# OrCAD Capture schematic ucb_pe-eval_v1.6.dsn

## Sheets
1 Interface-Power: size C; title: NCREPT PE-Eval PCB; rev: 1.5; company: University of Arkansas (NCREPT); note: 700 W. Research Center Blvd; note: Fayetteville, AR 72701
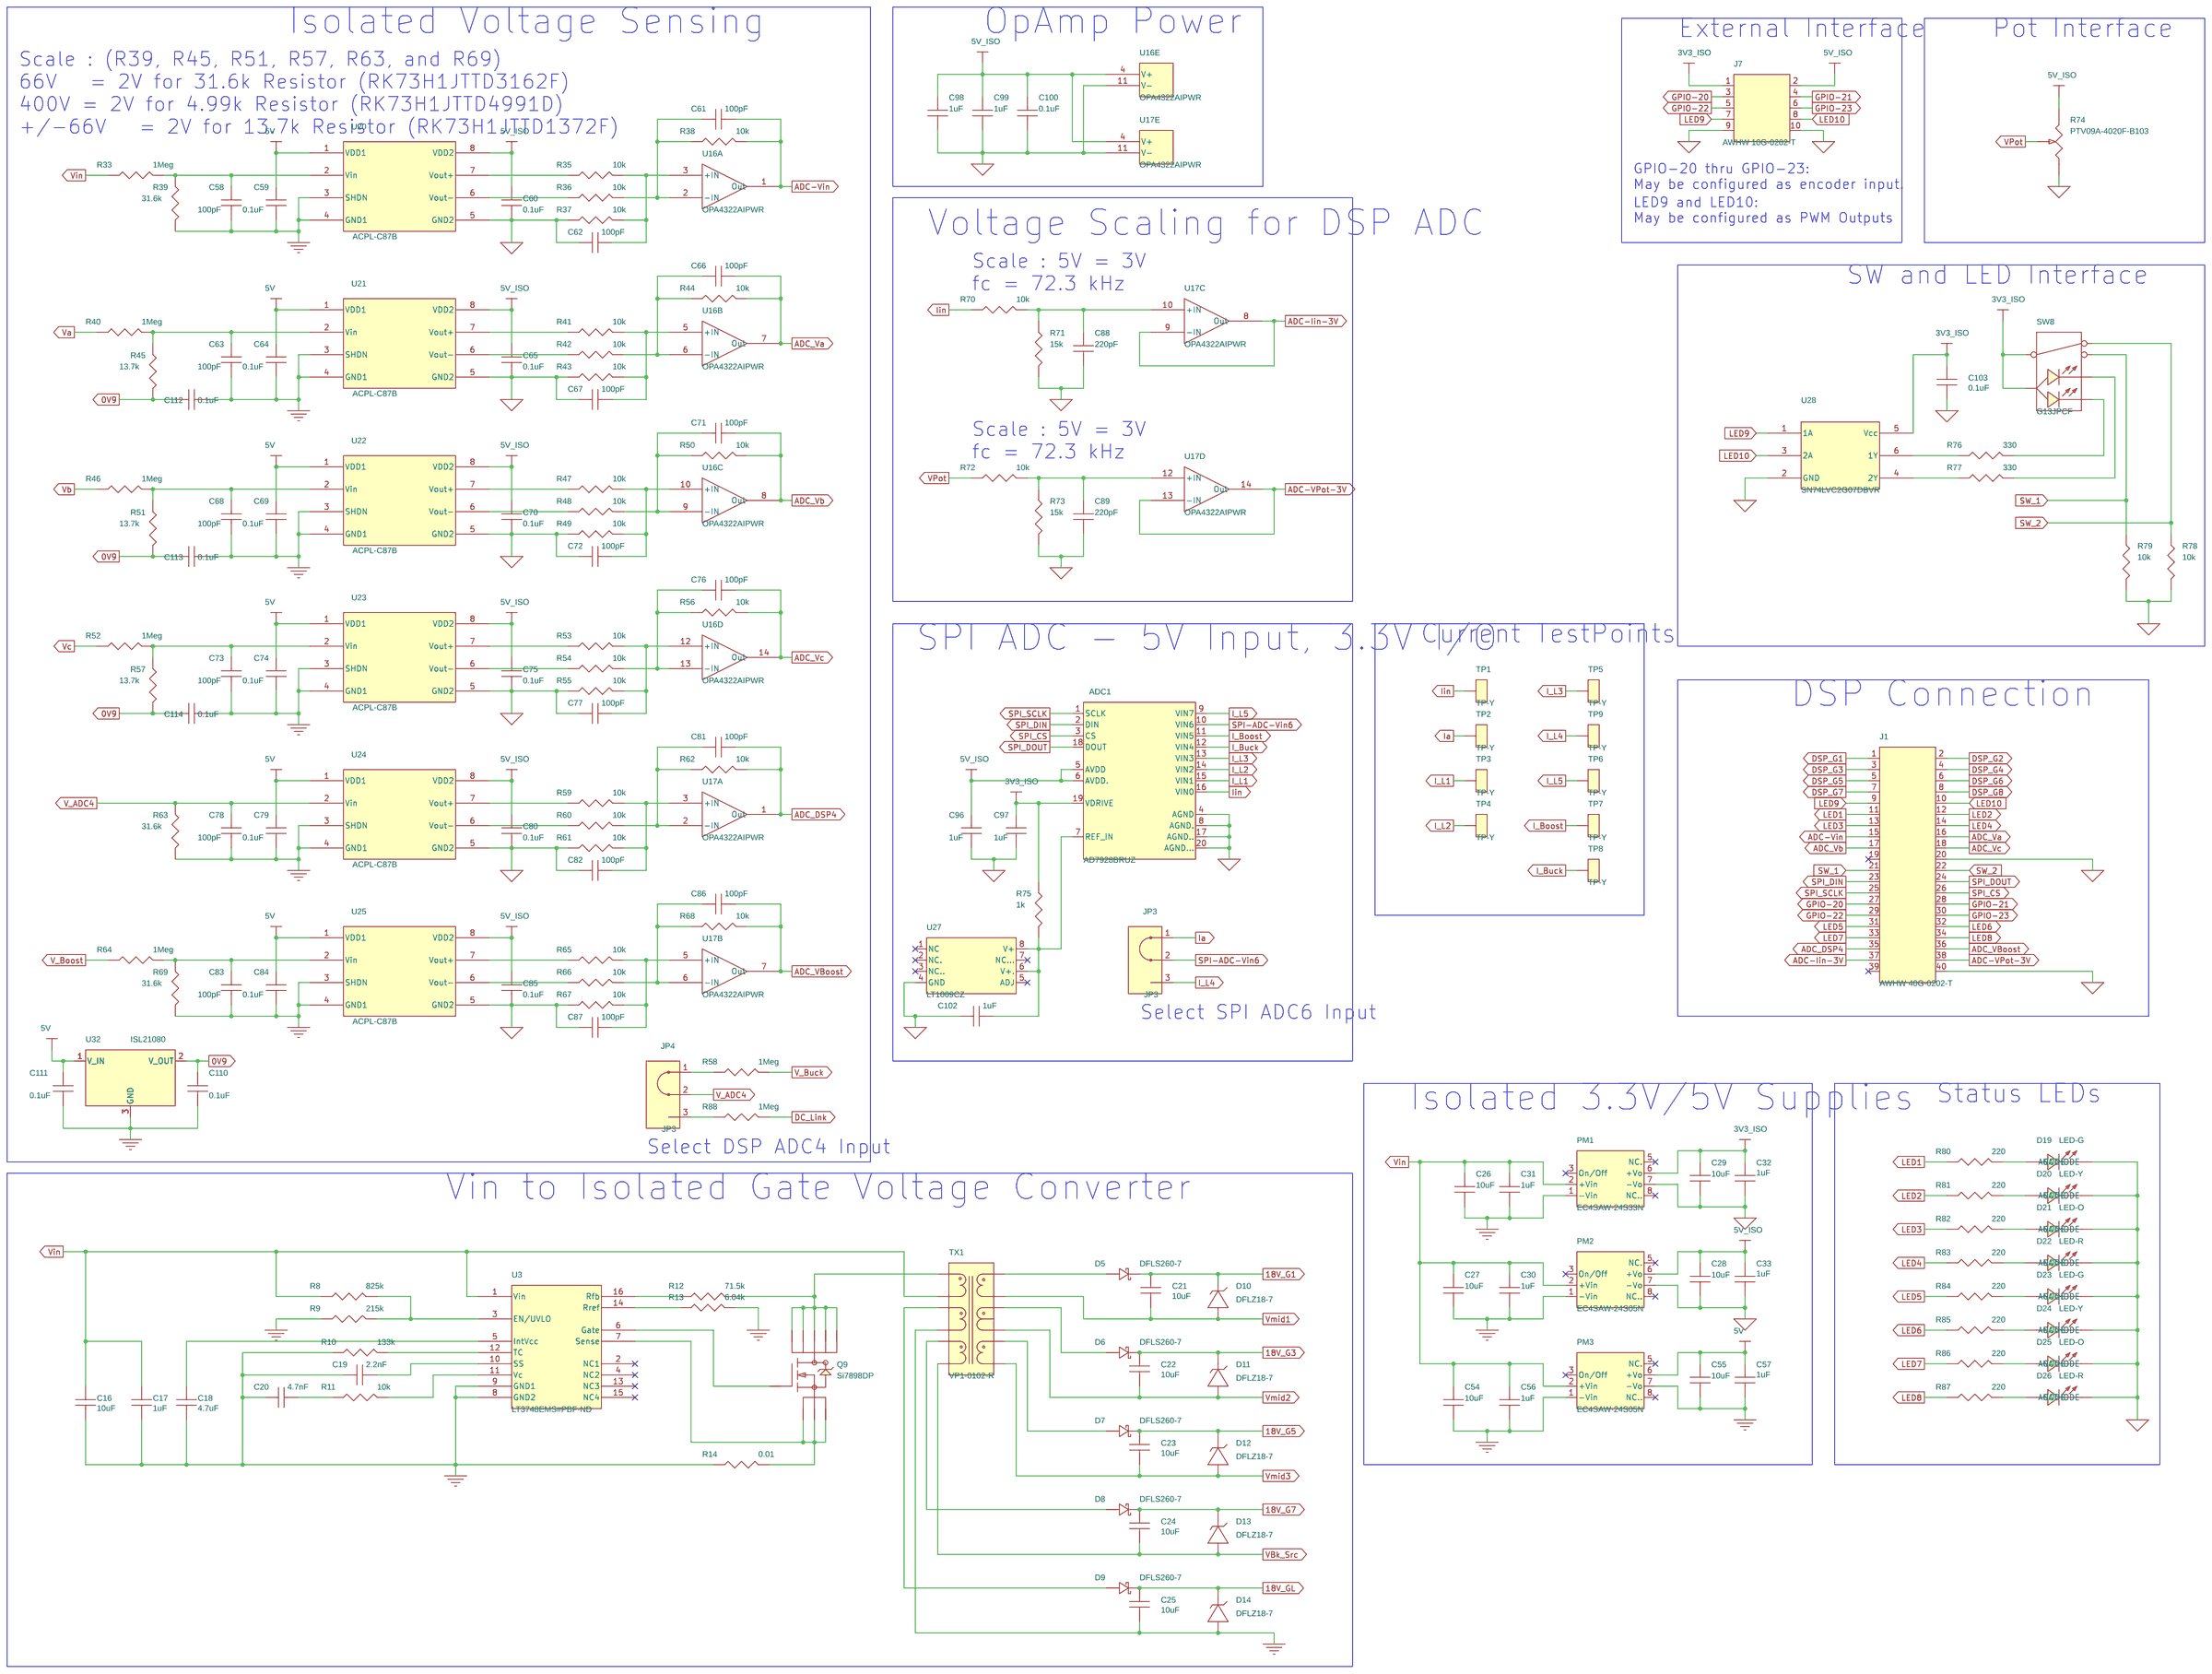
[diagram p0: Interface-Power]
2 Converters: size C
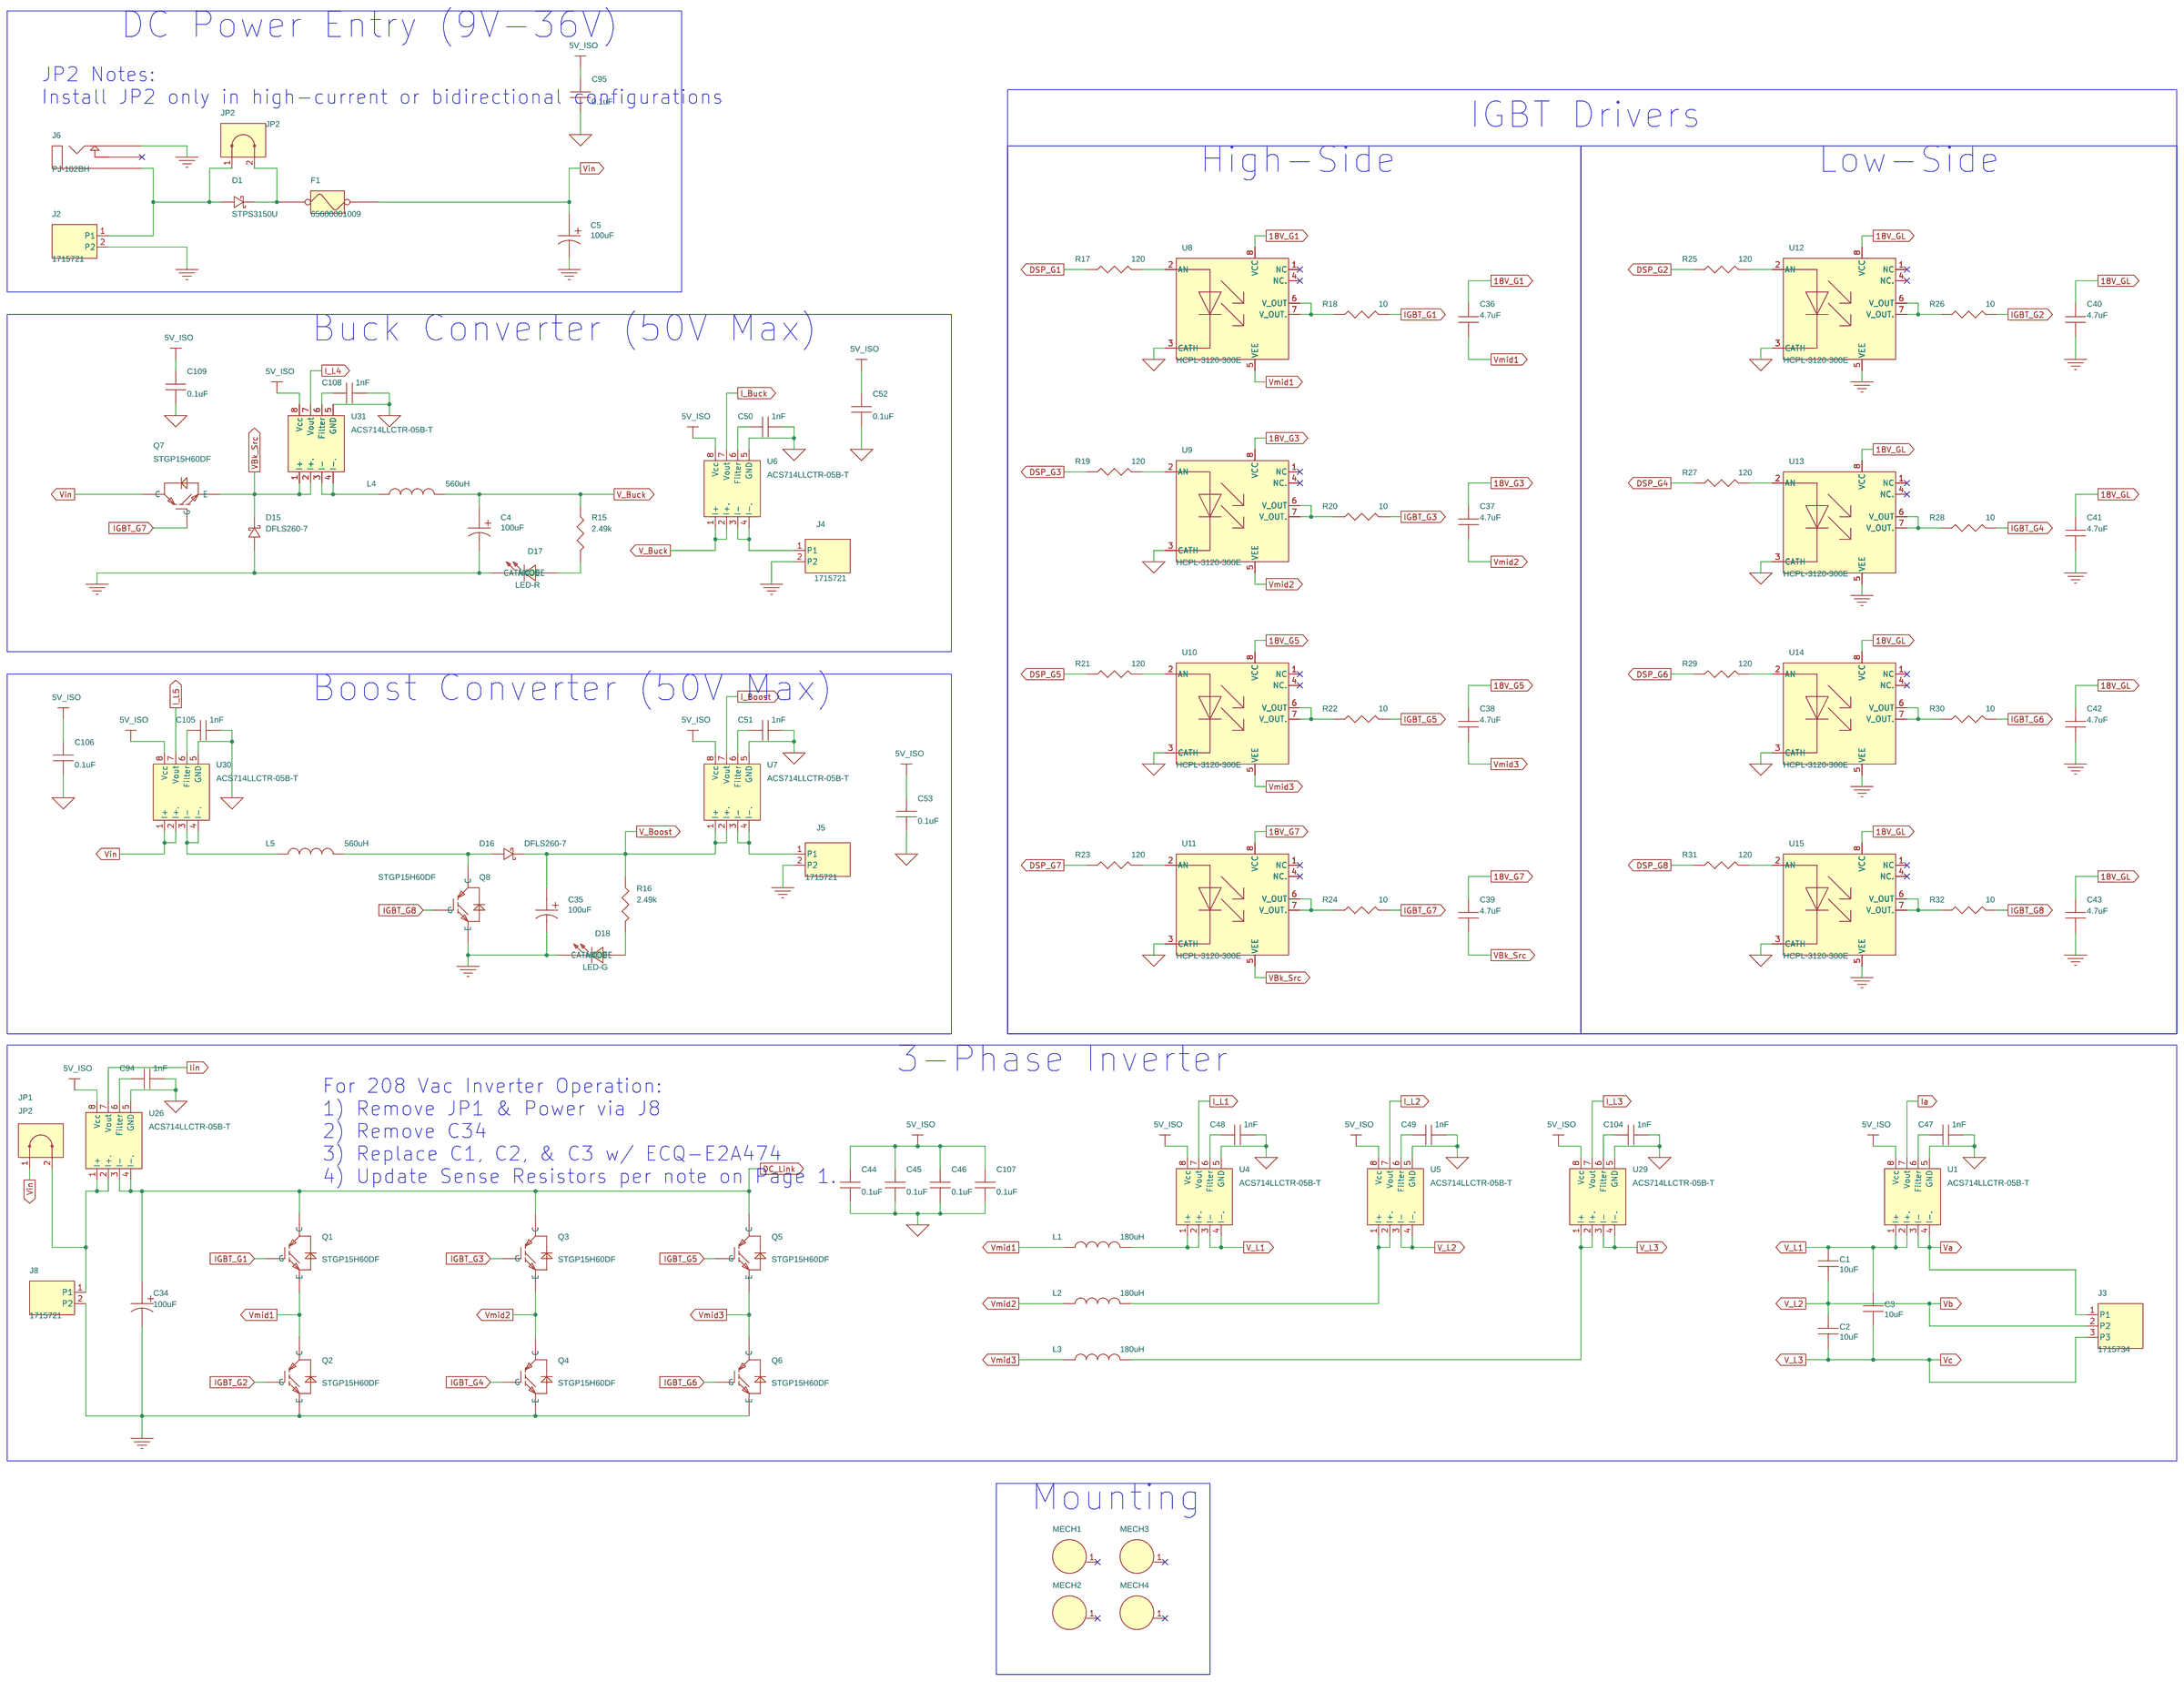
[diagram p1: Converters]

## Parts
sheet Converters
C1  10uF  [ECQ-E2106KFB]
C2  10uF  [ECQ-E2106KFB]
C3  10uF  [ECQ-E2106KFB]
C4  100uF  [UVZ1H101MPD]
C5  100uF  [UVZ1H101MPD]
C34  100uF  [UVZ1H101MPD]
C35  100uF  [UVZ1H101MPD]
C36  4.7uF  [C_1206]
C37  4.7uF  [C_1206]
C38  4.7uF  [C_1206]
C39  4.7uF  [C_1206]
C40  4.7uF  [C_1206]
C41  4.7uF  [C_1206]
C42  4.7uF  [C_1206]
C43  4.7uF  [C_1206]
C44  0.1uF  [C_0603]
C45  0.1uF  [C_0603]
C46  0.1uF  [C_0603]
C47  1nF  [C_0603]
C48  1nF  [C_0603]
C49  1nF  [C_0603]
C50  1nF  [C_0603]
C51  1nF  [C_0603]
C52  0.1uF  [C_0603]
C53  0.1uF  [C_0603]
C94  1nF  [C_0603]
C95  0.1uF  [C_0603]
C104  1nF  [C_0603]
C105  1nF  [C_0603]
C106  0.1uF  [C_0603]
C107  0.1uF  [C_0603]
C108  1nF  [C_0603]
C109  0.1uF  [C_0603]
D1  STPS3150U  [DO-214AA_SMB]
D15  DFLS260-7  [PowerDI-123]
D16  DFLS260-7  [PowerDI-123]
D17  LED-R  [LED_0805-RED]
D18  LED-G  [LED_0805-GREEN]
F1  65600001009  [FUSE_5X20MM]
J2  1715721  [1715721]
J3  1715734  [1715734]
J4  1715721  [1715721]
J5  1715721  [1715721]
J6  PJ-102BH  [DC-PWR_JACK]
J8  1715721  [1715721]
JP1  JP2  [J_1X2]
JP2  JP2  [J_1X2]
L1  180uH  [PCV-2-184-05L]
L2  180uH  [PCV-2-184-05L]
L3  180uH  [PCV-2-184-05L]
L4  560uH  [PCV-2-564-02L]
L5  560uH  [PCV-2-564-02L]
MECH1  Mech_Hole  [4-40_SCREW]
MECH2  Mech_Hole  [4-40_SCREW]
MECH3  Mech_Hole  [4-40_SCREW]
MECH4  Mech_Hole  [4-40_SCREW]
Q1  STGP15H60DF  [TO-220]
Q2  STGP15H60DF  [TO-220]
Q3  STGP15H60DF  [TO-220]
Q4  STGP15H60DF  [TO-220]
Q5  STGP15H60DF  [TO-220]
Q6  STGP15H60DF  [TO-220]
Q7  STGP15H60DF  [TO-220]
Q8  STGP15H60DF  [TO-220]
R15  2.49k  [R_2512]
R16  2.49k  [R_2512]
R17  120  [R_1206]
R18  10  [R_1206]
R19  120  [R_1206]
R20  10  [R_1206]
R21  120  [R_1206]
R22  10  [R_1206]
R23  120  [R_1206]
R24  10  [R_1206]
R25  120  [R_1206]
R26  10  [R_1206]
R27  120  [R_1206]
R28  10  [R_1206]
R29  120  [R_1206]
R30  10  [R_1206]
R31  120  [R_1206]
R32  10  [R_1206]
U1  ACS714LLCTR-05B-T  [8-SOIC]
U4  ACS714LLCTR-05B-T  [8-SOIC]
U5  ACS714LLCTR-05B-T  [8-SOIC]
U6  ACS714LLCTR-05B-T  [8-SOIC]
U7  ACS714LLCTR-05B-T  [8-SOIC]
U8  HCPL-3120-300E  [8-DIP_GW]
U9  HCPL-3120-300E  [8-DIP_GW]
U10  HCPL-3120-300E  [8-DIP_GW]
U11  HCPL-3120-300E  [8-DIP_GW]
U12  HCPL-3120-300E  [8-DIP_GW]
U13  HCPL-3120-300E  [8-DIP_GW]
U14  HCPL-3120-300E  [8-DIP_GW]
U15  HCPL-3120-300E  [8-DIP_GW]
U26  ACS714LLCTR-05B-T  [8-SOIC]
U29  ACS714LLCTR-05B-T  [8-SOIC]
U30  ACS714LLCTR-05B-T  [8-SOIC]
U31  ACS714LLCTR-05B-T  [8-SOIC]
sheet Interface-Power
ADC1  AD7928BRUZ  [20-TSSOP]
C16  10uF  [C_1206]
C17  1uF  [C_0603]
C18  4.7uF  [C_1206]
C19  2.2nF  [C_0603]
C20  4.7nF  [C_0603]
C21  10uF  [C_1206]
C22  10uF  [C_1206]
C23  10uF  [C_1206]
C24  10uF  [C_1206]
C25  10uF  [C_1206]
C26  10uF  [C_1206]
C27  10uF  [C_1206]
C28  10uF  [C_1206]
C29  10uF  [C_1206]
C30  1uF  [C_0603]
C31  1uF  [C_0603]
C32  1uF  [C_0603]
C33  1uF  [C_0603]
C54  10uF  [C_1206]
C55  10uF  [C_1206]
C56  1uF  [C_0603]
C57  1uF  [C_0603]
C58  100pF  [C_0603]
C59  0.1uF  [C_0603]
C60  0.1uF  [C_0603]
C61  100pF  [C_0603]
C62  100pF  [C_0603]
C63  100pF  [C_0603]
C64  0.1uF  [C_0603]
C65  0.1uF  [C_0603]
C66  100pF  [C_0603]
C67  100pF  [C_0603]
C68  100pF  [C_0603]
C69  0.1uF  [C_0603]
C70  0.1uF  [C_0603]
C71  100pF  [C_0603]
C72  100pF  [C_0603]
C73  100pF  [C_0603]
C74  0.1uF  [C_0603]
C75  0.1uF  [C_0603]
C76  100pF  [C_0603]
C77  100pF  [C_0603]
C78  100pF  [C_0603]
C79  0.1uF  [C_0603]
C80  0.1uF  [C_0603]
C81  100pF  [C_0603]
C82  100pF  [C_0603]
C83  100pF  [C_0603]
C84  0.1uF  [C_0603]
C85  0.1uF  [C_0603]
C86  100pF  [C_0603]
C87  100pF  [C_0603]
C88  220pF  [C_0603]
C89  220pF  [C_0603]
C96  1uF  [C_0603]
C97  1uF  [C_0603]
C98  1uF  [C_0603]
C99  1uF  [C_0603]
C100  0.1uF  [C_0603]
C102  1uF  [C_0603]
C103  0.1uF  [C_0603]
C110  0.1uF  [C_0603]
C111  0.1uF  [C_0603]
C112  0.1uF  [C_0603]
C113  0.1uF  [C_0603]
C114  0.1uF  [C_0603]
D5  DFLS260-7  [PowerDI-123]
D6  DFLS260-7  [PowerDI-123]
D7  DFLS260-7  [PowerDI-123]
D8  DFLS260-7  [PowerDI-123]
D9  DFLS260-7  [PowerDI-123]
D10  DFLZ18-7  [PowerDI-123]
D11  DFLZ18-7  [PowerDI-123]
D12  DFLZ18-7  [PowerDI-123]
D13  DFLZ18-7  [PowerDI-123]
D14  DFLZ18-7  [PowerDI-123]
D19  LED-G  [LED_0805-GREEN]
D20  LED-Y  [LED_0805-YELLOW]
D21  LED-O  [LED_0805-ORANGE]
D22  LED-R  [LED_0805-RED]
D23  LED-G  [LED_0805-GREEN]
D24  LED-Y  [LED_0805-YELLOW]
D25  LED-O  [LED_0805-ORANGE]
D26  LED-R  [LED_0805-RED]
J1  AWHW 40G-0202-T  [40-IDC-M]
J7  AWHW 10G-0202-T  [10-IDC-M]
JP3  JP3  [J_1X3]
JP4  JP3  [J_1X3]
PM1  EC4SAW-24S33N  [SIP-8]
PM2  EC4SAW-24S05N  [SIP-8]
PM3  EC4SAW-24S05N  [SIP-8]
Q9  Si7898DP  [SO-8_PP]
R8  825k  [R_0603]
R9  215k  [R_0603]
R10  133k  [R_0603]
R11  10k  [R_0603]
R12  71.5k  [R_0603]
R13  6.04k  [R_0603]
R14  0.01  [R_1206]
R33  1Meg  [R_1206]
R35  10k  [R_0603]
R36  10k  [R_0603]
R37  10k  [R_0603]
R38  10k  [R_0603]
R39  31.6k  [R_0805]
R40  1Meg  [R_1206]
R41  10k  [R_0603]
R42  10k  [R_0603]
R43  10k  [R_0603]
R44  10k  [R_0603]
R45  13.7k  [R_0603]
R46  1Meg  [R_1206]
R47  10k  [R_0603]
R48  10k  [R_0603]
R49  10k  [R_0603]
R50  10k  [R_0603]
R51  13.7k  [R_0603]
R52  1Meg  [R_1206]
R53  10k  [R_0603]
R54  10k  [R_0603]
R55  10k  [R_0603]
R56  10k  [R_0603]
R57  13.7k  [R_0603]
R58  1Meg  [R_1206]
R59  10k  [R_0603]
R60  10k  [R_0603]
R61  10k  [R_0603]
R62  10k  [R_0603]
R63  31.6k  [R_0805]
R64  1Meg  [R_1206]
R65  10k  [R_0603]
R66  10k  [R_0603]
R67  10k  [R_0603]
R68  10k  [R_0603]
R69  31.6k  [R_0805]
R70  10k  [R_0603]
R71  15k  [R_0603]
R72  10k  [R_0603]
R73  15k  [R_0603]
R74  PTV09A-4020F-B103  [9MM_POT]
R75  1k  [R_0805]
R76  330  [R_0805]
R77  330  [R_0805]
R78  10k  [R_0603]
R79  10k  [R_0603]
R80  220  [R_0805]
R81  220  [R_0805]
R82  220  [R_0805]
R83  220  [R_0805]
R84  220  [R_0805]
R85  220  [R_0805]
R86  220  [R_0805]
R87  220  [R_0805]
R88  1Meg  [R_1206]
SW8  G13JPCF  [G13JPCF_TH]
TP1  TP-Y  [TP-YELLOW]
TP2  TP-Y  [TP-YELLOW]
TP3  TP-Y  [TP-YELLOW]
TP4  TP-Y  [TP-YELLOW]
TP5  TP-Y  [TP-YELLOW]
TP6  TP-Y  [TP-YELLOW]
TP7  TP-Y  [TP-YELLOW]
TP8  TP-Y  [TP-YELLOW]
TP9  TP-Y  [TP-YELLOW]
TX1  VP1-0102-R  [TX-VP1]
U3  LT3748EMS#PBF-ND  [16-MSOP]
U16  OPA4322AIPWR  [OPA4332_14-TSSOP]  (sections A,B,C,D,E)
U17  OPA4322AIPWR  [OPA4332_14-TSSOP]  (sections A,B,C,D,E)
U20  ACPL-C87B  [ACPL-C87X]
U21  ACPL-C87B  [ACPL-C87X]
U22  ACPL-C87B  [ACPL-C87X]
U23  ACPL-C87B  [ACPL-C87X]
U24  ACPL-C87B  [ACPL-C87X]
U25  ACPL-C87B  [ACPL-C87X]
U27  LT1009CZ  [8-MSOP]
U28  SN74LVC2G07DBVR  [SOT-23-6]
U32  ISL21080  [SOT_23-3]

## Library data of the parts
C1-C3 = CAP_NP: Film Capacitor, 10uF, 250Vdc; Manufacturer: Panasonic; Part_Number: Cap-00019; Tolerance: 10%; Voltage: 250V; Datasheet: Panasonic-ABD0000C179-947645.pdf
C4 C5 C34 C35 = CAP_P: Electrolytic Capacitor (50V/100uF); Manufacturer: Nichicon; Part_Number: Cap-00020; Voltage: 50V; Datasheet: Nicicon-e-uvz-880014.pdf
C18 C36-C43 = CAP_NP: 4.7µF ±10% 50V X7R MLCC; Manufacturer: TDK; Manufacturer_Part_Number: C3216X7R1H475K160AC; Part_Number: Cap-00015; Tolerance: 10%; Voltage: 50V; Datasheet: TDK-mlcc_commercial_general_en.pdf
C44-C46 C52 C53 C59 C60 C64 C65 C69 C70 C74 C75 C79 C80 C84 C85 C95 C100 C103 C106 C107 C109-C114 = CAP_NP: 0.1µF ±10% 50V X7R MLCC; Manufacturer: TDK; Manufacturer_Part_Number: C1608X7R1H104K080AA; Part_Number: Cap-00001; Tolerance: 10%; Voltage: 50V; Datasheet: TDK-mlcc_commercial_general_en.pdf
C47-C51 C94 C104 C105 C108 = CAP_NP: 1nF ±10% 100V X7R MLCC; Manufacturer: TDK; Manufacturer_Part_Number: C1608X7R2A102K080AA; Part_Number: Cap-00005; Tolerance: 10%; Voltage: 100V; Datasheet: TDK-mlcc_commercial_general_en.pdf
D1 = D-Schottky: Schottky Diode 3A/150V; Manufacturer: ST; Part_Number: D-00001; STEP_Model: Diode SMA.stp; Datasheet: ST-en.CD00003323.pdf
D5-D9 D15 D16 = D-Schottky: Schottky Diode 2A/60V; Manufacturer: Diodes Incorporated; Part_Number: D-00005; STEP_Model: POWERDI-123.stp; Datasheet: DiodesInc-ds31476-56424.pdf
D17 D22 D26 = LED: LED, 0805, Red, VF= 1.8V; Manufacturer: OSRAM; Manufacturer_Part_Number: LH R974-LP-1; Part_Number: D-00007; STEP_Model: LED_0805-Red.stp; Datasheet: OSRAM-LHR974-CHIPLED0805-318659.pdf
D18 D19 D23 = LED: LED, 0805, Green, VF= 2.2V; Manufacturer: OSRAM; Manufacturer_Part_Number: LG R971-KN-1; Part_Number: D-00008; STEP_Model: LED_0805-Green.stp; Datasheet: OSRAM-LGR971-CHIPLED-0805-318376.pdf
F1 = FUSEHOLDER: Fuse Holder, 5x20mm, TH; Manufacturer: Littelfuse; Part_Number: F-00001; Datasheet: Littelfuse-656_659_660_LF_060102-16982.pdf
J2 J4 J5 J8 = Connector-2: PCB Terminal Block, 2-position, 90 degrees, 5.08mm; Manufacturer: Phoenix Contact; Part_Number: Con-00006; Rating: 17.5A; STEP_Model: 1715721.stp; Voltage: 400V; Datasheet: PhoenixContact-1715734.pdf
J3 = Connector-3: PCB Terminal Block, 3-position, 90 degrees, 5.08mm; Manufacturer: Phoenix Contact; Part_Number: Con-00007; Rating: 17.5A; STEP_Model: 1715734.stp; Voltage: 400V; Datasheet: PhoenixContact-1715734.pdf
J6 = DC-Jack_3: DC Power Jack, 2.5mm Center Pin, TH; Manufacturer: CUI; Part_Number: Con-00017; STEP_Model: pj-102bh.stp; Datasheet: CUI-PJ-102BH-524153.pdf
JP1 JP2 = JP2: Male, TH, Straight, 2-Pos, 0.1" Pitch; Manufacturer: Various; Manufacturer_Part_Number: PRT-00116; Part_Number: JP-00001
L1-L3 = Ind: 180uH, 4.0A, PCV-2; Manufacturer: CoilCraft; Part_Number: Ind-00009; Rating: 4A; Tolerance: 10%; Datasheet: CoilCraft-pcv.pdf
L4 L5 = Ind: 560uH, 2.6A, PCV-2; Manufacturer: CoilCraft; Part_Number: Ind-00010; Rating: 2.6A; Tolerance: 10%; Datasheet: CoilCraft-pcv.pdf
MECH1-MECH4 = Mech_Hole: Mounting Hole for 4-40 Screw, 0.125"; Part_Number: Con-00005
Q1-Q8 = IGBT_TO220: IGBT Trench gate 600V 15A; Manufacturer: STMicroelectrionics; Part_Number: Q-00004; STEP_Model: TO-220 3pins short V1.stp; Datasheet: ST-stgb15h60df-955853.pdf
R15 R16 = R-Standard: 2.49k Ohm, 1%, 2512; Manufacturer: KOA Speer; Manufacturer_Part_Number: RK73H3ATTE2491F; Part_Number: Res-00044; Rating: 1W; Tolerance: 1%; Datasheet: KOA-RK73H-5715.pdf
R17 R19 R21 R23 R25 R27 R29 R31 = R-Standard: 120 Ohm, 1%, 1206; Manufacturer: KOA Speer; Manufacturer_Part_Number: RK73H2BTTD1200F; Part_Number: Res-00041; Rating: 0.25W; Tolerance: 1%; Datasheet: KOA-RK73H-5715.pdf
R18 R20 R22 R24 R26 R28 R30 R32 = R-Standard: 10 Ohm, 1%, 1206; Manufacturer: KOA Speer; Manufacturer_Part_Number: RK73H2BTTD10R0F; Part_Number: Res-00008; Rating: 0.25W; Tolerance: 1%; Datasheet: KOA-RK73H-5715.pdf
U1 U4-U7 U26 U29-U31 = ACS714: Hall Effect Sensor, 5A AC/DC,185mV/A; Manufacturer: Allegro; Part_Number: IC-00016; Tolerance: 1.50%; Datasheet: Allegro-ACS714-Datasheet.pdf
U8-U15 = HCPL-3120: 2.5 Amp  IGBT Gate Drive, Optocoupler, Gullwing; Manufacturer: Avago; Part_Number: IC-00022; STEP_Model: 8-pin-DIP_GW_HCPL-300E.stp; Datasheet: Avago-AV02-0161EN_DS_HCPL-3120_2016-03-21.pdf
ADC1 = AD7928BRUZ: ADC 8-Ch, 12-Bit, 1MSPS; Manufacturer: Analog Devices; Part_Number: IC-00023; STEP_Model: TSSOP65P640X120-20N.stp; Datasheet: AnalogDevices-AD7908_7918_7928-877555.pdf
C16 C21-C29 C54 C55 = CAP_NP: 10µF ±20% 35V X7R MLCC; Manufacturer: TDK; Manufacturer_Part_Number: C3216X7R1V106M160AC; Part_Number: Cap-00002; Tolerance: 20%; Voltage: 35V; Datasheet: TDK-mlcc_commercial_general_en.pdf
C17 C30-C33 C56 C57 C96-C99 C102 = CAP_NP: 1µF ±10% 35V X7R MLCC; Manufacturer: TDK; Manufacturer_Part_Number: C1608X7R1V105K080AC; Part_Number: Cap-00008; Tolerance: 10%; Voltage: 35V; Datasheet: TDK-mlcc_commercial_general_en.pdf
C19 = CAP_NP: 2.2nF ±10% 100V X7R MLCC; Manufacturer: TDK; Manufacturer_Part_Number: C1608X7R2A222K080AA; Part_Number: Cap-00016; Tolerance: 10%; Voltage: 100V; Datasheet: TDK-mlcc_commercial_general_en.pdf
C20 = CAP_NP: 4.7nF ±10% 100V X7R MLCC; Manufacturer: TDK; Manufacturer_Part_Number: C1608X7R2A472K080AA; Part_Number: Cap-00017; Tolerance: 10%; Voltage: 100V; Datasheet: TDK-mlcc_commercial_general_en.pdf
C58 C61-C63 C66-C68 C71-C73 C76-C78 C81-C83 C86 C87 = CAP_NP: 100pF ±10% 100V C0G MLCC; Manufacturer: TDK; Manufacturer_Part_Number: C1608C0G2A101K080AA; Part_Number: Cap-00013; Tolerance: 10%; Voltage: 100V; Datasheet: TDK-mlcc_commercial_general_en.pdf
C88 C89 = CAP_NP: 0.22nF ±5% 100V C0G MLCC; Manufacturer: TDK; Manufacturer_Part_Number: C1608C0G2A221J080AA; Part_Number: Cap-00018; Tolerance: 5%; Voltage: 100V; Datasheet: TDK-mlcc_commercial_general_en.pdf
D10-D14 = D-Zener: Zener Diode 18V 1W; Manufacturer: Diodes Incorporated; Part_Number: D-00003; STEP_Model: POWERDI-123.stp; Tolerance: 6%; Datasheet: DiodesInc-ds30464.pdf
D20 D24 = LED: LED, 0805, Yellow, VF= 2.0V; Manufacturer: OSRAM; Manufacturer_Part_Number: LY R976-PS-36; Part_Number: D-00009; STEP_Model: LED_0805-Yellow.stp; Datasheet: OSRAM-LYR976-CHIPLED0805-318976.pdf
D21 D25 = LED: LED, 0805, Orange, VF= 2.0V; Manufacturer: OSRAM; Manufacturer_Part_Number: LO R976-PS-1; Part_Number: D-00010; STEP_Model: LED_0805-Orange.stp; Datasheet: OSRAM-LOR976-CHIPLED0805-318582.pdf
J1 = Header_2x20: 40-POS Header, Shrouded, 0.100", TH; Manufacturer: Assmann; Part_Number: Con-00015; STEP_Model: HDB-40.stp; User_Field1: SBH11-PBPC-D20-ST-BK; Datasheet: Assmann-AWHW-xxG-0x02-T.pdf
J7 = Header_2x5: 10-POS Header, Shrouded, 0.100", TH; Manufacturer: Assmann; Part_Number: Con-00013; STEP_Model: HDB-10.stp; User_Field1: SBH11-PBPC-D05-ST-BK; Datasheet: Assmann-AWHW-xxG-0x02-T.pdf
JP3 JP4 = JP3: Male, TH, Straight, 3-Pos, 0.1" Pitch; Manufacturer: Various; Manufacturer_Part_Number: PRT-00116; Part_Number: JP-00002
PM1 = EC4SA: Isolated DC/DC Converters 5 Watt, 9-36 Vin, 3.3 Vout; Manufacturer: Cincon; Part_Number: PS-00001; STEP_Model: PwrMod-SIP8.stp; Tolerance: 1.50%; Datasheet: CINCON-EC4SAW V10-557886.pdf
PM2 PM3 = EC4SA: Isolated DC/DC Converters 6 Watt, 9-36 Vin, 5 Vout; Manufacturer: Cincon; Part_Number: PS-00002; STEP_Model: PwrMod-SIP8.stp; Tolerance: 1.50%; Datasheet: CINCON-EC4SAW V10-557886.pdf
Q9 = N-FET_Si7898DP: Si N-Chan MOSFET 150V/3A; Manufacturer: Vishay; Manufacturer_Part_Number: SI7898DP-T1-E3; Part_Number: Q-00003; STEP_Model: SO-8.stp; Datasheet: Vishay-71873.pdf
R8 = R-Standard: 825k Ohm, 1%, 0603; Manufacturer: KOA Speer; Manufacturer_Part_Number: RK73H1JTTD8253F; Part_Number: Res-00025; Rating: 0.1W; Tolerance: 1%; Datasheet: KOA-RK73H-5715.pdf
R9 = R-Standard: 215k Ohm, 1%, 0603; Manufacturer: KOA Speer; Manufacturer_Part_Number: RK73H1JTTD2153F; Part_Number: Res-00057; Rating: 0.1W; Tolerance: 1%; Datasheet: KOA-RK73H-5715.pdf
R10 = R-Standard: 133k Ohm, 1%, 0603; Manufacturer: KOA Speer; Manufacturer_Part_Number: RK73H1JTTD1333F; Part_Number: Res-00030; Rating: 0.1W; Tolerance: 1%; Datasheet: KOA-RK73H-5715.pdf
R11 R35-R38 R41-R44 R47-R50 R53-R56 R59-R62 R65-R68 R70 R72 R78 R79 = R-Standard: 10k Ohm, 1%, 0603; Manufacturer: KOA Speer; Manufacturer_Part_Number: RK73H1JTTD1002F; Part_Number: Res-00031; Rating: 0.1W; Tolerance: 1%; Datasheet: KOA-RK73H-5715.pdf
R12 = R-Standard: 71.5k Ohm, 1%, 0603; Manufacturer: KOA Speer; Manufacturer_Part_Number: RK73H1JTTD7152F; Part_Number: Res-00027; Rating: 0.1W; Tolerance: 1%; Datasheet: KOA-RK73H-5715.pdf
R13 = R-Standard: 6.04k Ohm, 1%, 0603; Manufacturer: KOA Speer; Manufacturer_Part_Number: RK73H1JTTD6041F; Part_Number: Res-00029; Rating: 0.1W; Tolerance: 1%; Datasheet: KOA-RK73H-5715.pdf
R14 = R-Standard: 10m Ohm, 1%, 1206, Current Sense Res; Manufacturer: KOA Speer; Manufacturer_Part_Number: UR73VD2BTTD10L0F; Part_Number: Res-00033; Rating: 0.5W; Tolerance: 1%; Datasheet: KOA-UR73V-770279.pdf
R33 R40 R46 R52 R58 R64 R88 = R-Standard: 1M Ohm, 1%,1206; Manufacturer: KOA Speer; Manufacturer_Part_Number: RK73H2BTTD1004F; Part_Number: Res-00034; Tolerance: 1%; Datasheet: KOA-RK73H-5715.pdf
R39 R63 R69 = R-Standard: 31.6k Ohm, 1%, 0603; Manufacturer: KOA Speer; Manufacturer_Part_Number: RK73H1JTTD3162F; Part_Number: Res-00022; Rating: 0.1W; Tolerance: 1%; Datasheet: KOA-RK73H-5715.pdf
R45 R51 R57 = R-Standard: 13.7k Ohm, 1%, 0603; Manufacturer: KOA Speer; Manufacturer_Part_Number: RK73H1JTTD1372F; Part_Number: TMP-372; Tolerance: 1%; Datasheet: KOA-RK73H-5715.pdf
R71 R73 = R-Standard: 15k Ohm, 1%, 0603; Manufacturer: KOA Speer; Manufacturer_Part_Number: RK73H1JTTD1502F; Part_Number: Res-00037; Rating: 0.1W; Tolerance: 1%; Datasheet: KOA-RK73H-5715.pdf
R74 = R-POT: Potentiometer 10k Linear, 6mm Shaft,TH; Manufacturer: Bourns; Part_Number: Res-00043; Tolerance: 20%; Datasheet: Bourns-tv09-777818.pdf
R75 = R-Standard: 1k Ohm, 1%, 0805; Manufacturer: KOA Speer; Manufacturer_Part_Number: RK73H2ATTD1001F; Part_Number: Res-00012; Rating: 0.125W; Tolerance: 1%; Datasheet: KOA-RK73H-5715.pdf
R76 R77 = R-Standard: 330 Ohm, 1%, 0805; Manufacturer: KOA Speer; Manufacturer_Part_Number: RK73H2ATTD3300F; Part_Number: Res-00040; Rating: 0.125W; Tolerance: 1%; Datasheet: KOA-RK73H-5715.pdf
R80-R87 = R-Standard: 220 Ohm, 1%, 0805; Manufacturer: KOA Speer; Manufacturer_Part_Number: RK73H2ATTD2200F; Part_Number: Res-00017; Rating: 0.125W; Tolerance: 1%; Datasheet: KOA-RK73H-5715.pdf
SW8 = SW_G13JPCF: Switch Toggle, SPDT, R/G LED (TH Pads); Manufacturer: NKK Switches; Part_Number: Sw-00002; Datasheet: NKK-gtogglesilluminated.pdf
TP1-TP9 = TP: PCB Test Point TH Yellow; Manufacturer: Keystone Electronics; Manufacturer_Part_Number: 5004; Part_Number: TP-00005; Datasheet: Keystone-000-5004-741320.pdf
TX1 = TX_VP1-0102-R: 6.5µH, 0.8A, 6-Winding XFMR, VTP1, 20%; Manufacturer: Eaton; Part_Number: XFRM-00002; Tolerance: 20%; Datasheet: Eaton-BUS_Elx_PM_4301_VERSA_PAC.pdf
U3 = LT3748EMS#PBF-ND: Flyback Controller (Used with VP1 Arrays); Manufacturer: Linear Tech; Part_Number: IC-00010; STEP_Model: MSOP-16_MSEP16-12.stp; Datasheet: LT-3748fb.pdf
U16 U17 = OPA4322AIPWR: Quad OpAmp, 20 MHz; Manufacturer: TI; Part_Number: IC-00012; STEP_Model: TSSOP14.stp; User_Field1: https://www.google.com/; Datasheet: TI-opa4322.pdf
U20-U25 = ACPL-C87B: Isolation OpAmp, 100 kHz; Manufacturer: Avago; Manufacturer_Part_Number: ACPL-C87B-000E; Part_Number: IC-00011; STEP_Model: SOIC08 wide.stp; Datasheet: Avago-AV02-3563EN_DS_ACPL-C87x_04Mar2013.pdf
U27 = LT1009CZ: 2.5V Voltage Reference, ±0.2%, SMD; Manufacturer: Linear Tech; Manufacturer_Part_Number: LT1009CMS8#PBF; Part_Number: IC-00024; STEP_Model: MSOP8.stp; Tolerance: 0.20%; Datasheet: LinearTech-1009ff.pdf
U28 = SN74LVC2G07DBV: Dual Open-Drain Buffer; Manufacturer: TI; Part_Number: IC-00013; STEP_Model: SOT23-6.stp; Datasheet: TI-sn74lvc2g07.pdf
U32 = ISL21080: 0.9V Voltage Reference, ±0.7%; Manufacturer: Intersil; Manufacturer_Part_Number: ISL21080DIH309Z-TK; Part_Number: IC-00014; Tolerance: 0.70%; Datasheet: Intersil-isl21080.pdf

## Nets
0V9: C110.1 C112.1 C113.1 C114.1 R45.2 R51.2 R57.2 U32.2(V_OUT)
3V3_Iso: ADC1.19(VDRIVE) C29.1 C32.1 C97.1 C103.1 J7.1 PM1.6(+Vo) R75.1 SW8.2(COMMON) SW8.5(CA) U28.5(Vcc)
5V: C55.1 C57.1 C59.1 C64.1 C69.1 C74.1 C79.1 C84.1 C111.1 PM3.6(+Vo) U20.1(VDD1) U21.1(VDD1) U22.1(VDD1) U23.1(VDD1) U24.1(VDD1) U25.1(VDD1) U32.1(V_IN)
5V_Iso: ADC1.5(AVDD) ADC1.6(AVDD.) C28.1 C33.1 C44.1 C45.1 C46.1 C52.1 C53.1 C60.1 C65.1 C70.1 C75.1 C80.1 C85.1 C95.1 C96.1 C98.1 C99.1 C100.1 C106.1 C107.1 C109.1 J7.2 PM2.6(+Vo) R74.3(B) U1.8(Vcc) U4.8(Vcc) U5.8(Vcc) U6.8(Vcc) U7.8(Vcc) U16.4(V+) U17.4(V+) U20.8(VDD2) U21.8(VDD2) U22.8(VDD2) U23.8(VDD2) U24.8(VDD2) U25.8(VDD2) U26.8(Vcc) U29.8(Vcc) U30.8(Vcc) U31.8(Vcc)
18V_G1: C21.1 C36.1 D5.1 D10.1 U8.8(VCC)
18V_G3: C22.1 C37.1 D6.1 D11.1 U9.8(VCC)
18V_G5: C23.1 C38.1 D7.1 D12.1 U10.8(VCC)
18V_G7: C24.1 C39.1 D8.1 D13.1 U11.8(VCC)
18V_GL: C25.1 C40.1 C41.1 C42.1 C43.1 D9.1 D14.1 U12.8(VCC) U13.8(VCC) U14.8(VCC) U15.8(VCC)
GND: C4.2 C5.2 C16.2 C17.2 C18.2 C19.1 C20.1 C25.2 C26.2 C27.2 C30.2 C31.2 C34.2 C35.2 C40.2 C41.2 C42.2 C43.2 C54.2 C55.2 C56.2 C57.2 C58.2 C59.2 C63.2 C64.2 C68.2 C69.2 C73.2 C74.2 C78.2 C79.2 C83.2 C84.2 C110.2 C111.2 C112.2 C113.2 C114.2 D14.2 D15.2 D17.1(CATHODE) D18.1(CATHODE) J2.2(P2) J4.2(P2) J5.2(P2) J6.2 J8.2(P2) PM1.1(-Vin) PM2.1(-Vin) PM3.1(-Vin) PM3.7(-Vo) Q2.3(E) Q4.3(E) Q6.3(E) Q8.3(E) R9.1 R10.1 R13.2 R14.1 R39.2 R63.2 R69.2 TX1.2 U3.8(GND2) U3.9(GND1) U12.5(VEE) U13.5(VEE) U14.5(VEE) U15.5(VEE) U20.3(SHDN) U20.4(GND1) U21.3(SHDN) U21.4(GND1) U22.3(SHDN) U22.4(GND1) U23.3(SHDN) U23.4(GND1) U24.3(SHDN) U24.4(GND1) U25.3(SHDN) U25.4(GND1) U32.3(GND)
GND_SIGNAL: ADC1.4(AGND) ADC1.8(AGND.) ADC1.17(AGND..) ADC1.20(AGND...) C28.2 C29.2 C32.2 C33.2 C44.2 C45.2 C46.2 C47.2 C48.2 C49.2 C50.2 C51.2 C52.2 C53.2 C60.2 C62.1 C65.2 C67.1 C70.2 C72.1 C75.2 C77.1 C80.2 C82.1 C85.2 C87.1 C88.2 C89.2 C94.2 C95.2 C96.2 C97.2 C98.2 C99.2 C100.2 C102.1 C103.2 C104.2 C105.2 C106.2 C107.2 C108.2 C109.2 D19.1(CATHODE) D20.1(CATHODE) D21.1(CATHODE) D22.1(CATHODE) D23.1(CATHODE) D24.1(CATHODE) D25.1(CATHODE) D26.1(CATHODE) J1.20 J1.40 J7.9 J7.10 PM1.7(-Vo) PM2.7(-Vo) R37.1 R43.1 R49.1 R55.1 R61.1 R67.1 R71.2 R73.2 R74.1(A) R78.2 R79.2 U1.5(GND) U4.5(GND) U5.5(GND) U6.5(GND) U7.5(GND) U8.3(CATH) U9.3(CATH) U10.3(CATH) U11.3(CATH) U12.3(CATH) U13.3(CATH) U14.3(CATH) U15.3(CATH) U16.11(V-) U17.11(V-) U20.5(GND2) U21.5(GND2) U22.5(GND2) U23.5(GND2) U24.5(GND2) U25.5(GND2) U26.5(GND) U27.4(GND) U28.2(GND) U29.5(GND) U30.5(GND) U31.5(GND)
Vin: C5.1 C16.1 C17.1 C26.1 C27.1 C30.1 C31.1 C54.1 C56.1 F1.2 JP1.1 PM1.2(+Vin) PM2.2(+Vin) PM3.2(+Vin) Q7.2(C) R8.1 R33.1 TX1.1 U3.1(Vin) U30.1(I+) U30.2(I+.)
ADC-Iin-3V: J1.37 U17.8(Out) U17.9(-IN)
ADC-Vin: C61.2 J1.15 R38.2 U16.1(Out)
ADC-VPot-3V: J1.38 U17.13(-IN) U17.14(Out)
ADC_DSP4: C81.2 J1.35 R62.2 U17.1(Out)
ADC_Va: C66.2 J1.16 R44.2 U16.7(Out)
ADC_Vb: C71.2 J1.17 R50.2 U16.8(Out)
ADC_VBoost: C86.2 J1.36 R68.2 U17.7(Out)
ADC_Vc: C76.2 J1.18 R56.2 U16.14(Out)
DC_Link: C34.1 Q1.2(C) Q3.2(C) Q5.2(C) R88.2 U26.3(I-) U26.4(I-.)
DSP_G1: J1.1 R17.1
DSP_G2: J1.2 R25.1
DSP_G3: J1.3 R19.1
DSP_G4: J1.4 R27.1
DSP_G5: J1.5 R21.1
DSP_G6: J1.6 R29.1
DSP_G7: J1.7 R23.1
DSP_G8: J1.8 R31.1
GPIO-20: J1.27 J7.3
GPIO-21: J1.28 J7.4
GPIO-22: J1.29 J7.5
GPIO-23: J1.30 J7.6
I_Boost: ADC1.11(VIN5) TP7.1 U7.7(Vout)
I_Buck: ADC1.12(VIN4) TP8.1 U6.7(Vout)
I_L1: ADC1.15(VIN1) TP3.1 U4.7(Vout)
I_L2: ADC1.14(VIN2) TP4.1 U5.7(Vout)
I_L3: ADC1.13(VIN3) TP5.1 U29.7(Vout)
I_L4: JP3.3 TP9.1 U31.7(Vout)
I_L5: ADC1.9(VIN7) TP6.1 U30.7(Vout)
Ia: JP3.1 TP2.1 U1.7(Vout)
IGBT_G1: Q1.1(G) R18.2
IGBT_G2: Q2.1(G) R26.2
IGBT_G3: Q3.1(G) R20.2
IGBT_G4: Q4.1(G) R28.2
IGBT_G5: Q5.1(G) R22.2
IGBT_G6: Q6.1(G) R30.2
IGBT_G7: Q7.1(G) R24.2
IGBT_G8: Q8.1(G) R32.2
Iin: ADC1.16(VIN0) R70.1 TP1.1 U26.7(Vout)
LED1: J1.11 R80.1
LED2: J1.12 R81.1
LED3: J1.13 R82.1
LED4: J1.14 R83.1
LED5: J1.31 R84.1
LED6: J1.32 R85.1
LED7: J1.33 R86.1
LED8: J1.34 R87.1
LED9: J1.9 J7.7 U28.1(1A)
LED10: J1.10 J7.8 U28.3(2A)
SPI-ADC-Vin6: ADC1.10(VIN6) JP3.2
SPI_CS: ADC1.3(CS) J1.26
SPI_DIN: ADC1.2(DIN) J1.23
SPI_DOUT: ADC1.18(DOUT) J1.24
SPI_SCLK: ADC1.1(SCLK) J1.25
SW_1: J1.21 R79.1 SW8.3(NC)
SW_2: J1.22 R78.1 SW8.1(NO)
V_ADC4: C78.1 JP4.2 R63.1 U24.2(Vin)
V_Boost: C35.1 D16.1 R16.1 R64.1 U7.1(I+) U7.2(I+.)
V_Buck: C4.1 L4.2 R15.1 R58.2 U6.1(I+) U6.2(I+.)
V_L1: C1.1 C3.1 U1.1(I+) U1.2(I+.) U4.3(I-) U4.4(I-.)
Va: J3.1(P1) R40.1 U1.3(I-) U1.4(I-.)
Vb: C1.2 C2.1 J3.2(P2) R46.1 U5.3(I-) U5.4(I-.)
VBk_Src: C24.2 C39.2 D13.2 D15.1 Q7.3(E) TX1.3 U11.5(VEE) U31.1(I+) U31.2(I+.)
Vc: C2.2 C3.2 J3.3(P3) R52.1 U29.3(I-) U29.4(I-.)
Vmid1: C21.2 C36.2 D10.2 L1.1 Q1.3(E) Q2.2(C) TX1.7 U8.5(VEE)
Vmid2: C22.2 C37.2 D11.2 L2.1 Q3.3(E) Q4.2(C) TX1.8 U9.5(VEE)
Vmid3: C23.2 C38.2 D12.2 L3.1 Q5.3(E) Q6.2(C) TX1.9 U10.5(VEE)
VPot: R72.1 R74.2(WIPER)
N07970: R8.2 R9.2 U3.3(EN/UVLO)
N08403: C18.1 U3.5(IntVcc)
N08410: R10.2 U3.12(TC)
N08443: C19.2 U3.10(SS)
N08455: R11.2 U3.11(Vc)
N08467: C20.2 R11.1
N09759: Q9.1(S1) Q9.2(S2) Q9.3(S3) R14.2 U3.7(Sense)
N09873: Q9.5(D1) Q9.6(D2) Q9.7(D3) Q9.8(D4) Q9.9(D_EP) R12.2 TX1.4
N10901: Q9.4(G) U3.6(Gate)
N10913: R12.1 U3.16(Rfb)
N10917: R13.1 U3.14(Rref)
N11491: D7.2 TX1.12
N11495: D6.2 TX1.11
N11499: D5.2 TX1.10
N11507: D8.2 TX1.6
N11532: D9.2 TX1.5
N38522: D17.2(ANODE) R15.2
N38590: D16.2 L5.2 Q8.2(C)
N38634: D18.2(ANODE) R16.2
N38702: J4.1(P1) U6.3(I-) U6.4(I-.)
N38762: J5.1(P1) U7.3(I-) U7.4(I-.)
N41110: C50.1 U6.6(Filter)
N41352: C51.1 U7.6(Filter)
N42617: D1.2 J2.1(P1) J6.1 JP2.1
N42649: D1.1 F1.1 JP2.2
N48243: C62.2 R35.2 R37.2 U16.3(+IN)
N48256: R35.1 U20.7(Vout+)
N48260: R36.1 U20.6(Vout-)
N48264: C61.1 R36.2 R38.1 U16.2(-IN)
N48807: C58.1 R33.2 R39.1 U20.2(Vin)
N51115: C67.2 R41.2 R43.2 U16.5(+IN)
N51119: R41.1 U21.7(Vout+)
N51123: R42.1 U21.6(Vout-)
N51127: C66.1 R42.2 R44.1 U16.6(-IN)
N51265: C63.1 R40.2 R45.1 U21.2(Vin)
N52251: C72.2 R47.2 R49.2 U16.10(+IN)
N52255: R47.1 U22.7(Vout+)
N52259: R48.1 U22.6(Vout-)
N52263: C71.1 R48.2 R50.1 U16.9(-IN)
N52429: C68.1 R46.2 R51.1 U22.2(Vin)
N53429: C77.2 R53.2 R55.2 U16.12(+IN)
N53433: R53.1 U23.7(Vout+)
N53437: R54.1 U23.6(Vout-)
N53441: C76.1 R54.2 R56.1 U16.13(-IN)
N53607: C73.1 R52.2 R57.1 U23.2(Vin)
N54653: C82.2 R59.2 R61.2 U17.3(+IN)
N54657: R59.1 U24.7(Vout+)
N54661: R60.1 U24.6(Vout-)
N54665: C81.1 R60.2 R62.1 U17.2(-IN)
N56809: C87.2 R65.2 R67.2 U17.5(+IN)
N56813: R65.1 U25.7(Vout+)
N56817: R66.1 U25.6(Vout-)
N56821: C86.1 R66.2 R68.1 U17.6(-IN)
N56959: C83.1 R64.2 R69.1 U25.2(Vin)
N58569: C88.1 R70.2 R71.1 U17.10(+IN)
N59411: C89.1 R72.2 R73.1 U17.12(+IN)
N62015: C94.1 U26.6(Filter)
N62666: J8.1(P1) JP1.2 U26.1(I+) U26.2(I+.)
N71004: ADC1.7(REF_IN) C102.2 R75.2 U27.6(V+.) U27.8(V+)
N72702: R76.2 SW8.6(C_GRN)
N72714: R77.2 SW8.4(C_Red)
N72726: R77.1 U28.4(2Y)
N72730: R76.1 U28.6(1Y)
N126025: D19.2(ANODE) R80.2
N126027: D25.2(ANODE) R86.2
N126029: D24.2(ANODE) R85.2
N126031: D23.2(ANODE) R84.2
N126033: D22.2(ANODE) R83.2
N126035: D26.2(ANODE) R87.2
N126037: D21.2(ANODE) R82.2
N126039: D20.2(ANODE) R81.2
N176335: C47.1 U1.6(Filter)
N176535: C48.1 U4.6(Filter)
N176547: C49.1 U5.6(Filter)
N176863: L2.2 U5.1(I+) U5.2(I+.)
N176875: L3.2 U29.1(I+) U29.2(I+.)
N176963: L1.2 U4.1(I+) U4.2(I+.)
N179536: R17.2 U8.2(AN)
N179562: R18.1 U8.6(V_OUT) U8.7(V_OUT.)
N179712: R19.2 U9.2(AN)
N179754: R20.1 U9.6(V_OUT) U9.7(V_OUT.)
N179920: R21.2 U10.2(AN)
N179946: R22.1 U10.6(V_OUT) U10.7(V_OUT.)
N180096: R23.2 U11.2(AN)
N180138: R24.1 U11.6(V_OUT) U11.7(V_OUT.)
N180288: R25.2 U12.2(AN)
N180330: R26.1 U12.6(V_OUT) U12.7(V_OUT.)
N180476: R27.2 U13.2(AN)
N180502: R28.1 U13.6(V_OUT) U13.7(V_OUT.)
N180632: R29.2 U14.2(AN)
N180674: R30.1 U14.6(V_OUT) U14.7(V_OUT.)
N180804: R31.2 U15.2(AN)
N180846: R32.1 U15.6(V_OUT) U15.7(V_OUT.)
N220911: C104.1 U29.6(Filter)
N223775: C105.1 U30.6(Filter)
N223929: L5.1 U30.3(I-) U30.4(I-.)
N248745: C108.1 U31.6(Filter)
N249090: L4.1 U31.3(I-) U31.4(I-.)
N283243: JP4.3 R88.1
N283252: JP4.1 R58.1

Not connected (* = marked no-connect by the designer): J1 19* 39*; J6 3*; MECH1 1*; MECH2 1*; MECH3 1*; MECH4 1*; PM1 3(On/Off)* 5(NC.)* 8(NC..)*; PM2 3(On/Off)* 5(NC.)* 8(NC..)*; PM3 3(On/Off)* 5(NC.)* 8(NC..)*; U3 2(NC1)* 4(NC2)* 13(NC3)* 15(NC4)*; U8 1(NC)* 4(NC.)*; U9 1(NC)* 4(NC.)*; U10 1(NC)* 4(NC.)*; U11 1(NC)* 4(NC.)*; U12 1(NC)* 4(NC.)*; U13 1(NC)* 4(NC.)*; U14 1(NC)* 4(NC.)*; U15 1(NC)* 4(NC.)*; U27 1(NC)* 2(NC.)* 3(NC..)* 5(ADJ)* 7(NC...)*

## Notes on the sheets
sheet 1
- Isolated Voltage Sensing
- OpAmp Power
- External Interface
- Pot Interface
- Scale : (R39, R45, R51, R57, R63, and R69)
  66V   = 2V for 31.6k Resistor (RK73H1JTTD3162F)
  400V = 2V for 4.99k Resistor (RK73H1JTTD4991D)
  +/-66V   = 2V for 13.7k Resistor (RK73H1JTTD1372F)
- GPIO-20 thru GPIO-23:
  May be configured as encoder input.
- LED9 and LED10:
  May be configured as PWM Outputs
- Voltage Scaling for DSP ADC
- Scale : 5V = 3V
  fc = 72.3 kHz
- SW and LED Interface
- Scale : 5V = 3V
  fc = 72.3 kHz
- SPI ADC - 5V Input, 3.3V I/O
- Current TestPoints
- DSP Connection
- Select SPI ADC6 Input
- Isolated 3.3V/5V Supplies
- Status LEDs
- Select DSP ADC4 Input
- Vin to Isolated Gate Voltage Converter
sheet 2
- DC Power Entry (9V-36V)
- JP2 Notes:
  Install JP2 only in high-current or bidirectional configurations
- IGBT Drivers
- High-Side
- Low-Side
- Buck Converter (50V Max)
- Boost Converter (50V Max)
- 3-Phase Inverter
- For 208 Vac Inverter Operation:
  1) Remove JP1 & Power via J8
  2) Remove C34
  3) Replace C1, C2, & C3 w/ ECQ-E2A474
  4) Update Sense Resistors per note on Page 1.
- Mounting
